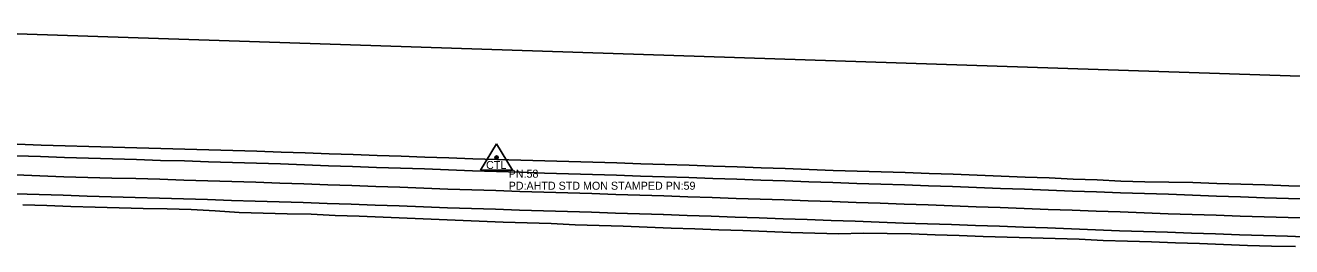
# Model space of a CAD drawing. Extents: x 976456 to 985170, y 1525951 to 1527080.
# Drawn here: x 979231 to 980022, y 1526411 to 1526549 of the extents above; entities that cross this region are included whole.
import ezdxf

# ---------------------------------------------------------------- set-up
doc = ezdxf.new("R2010")
doc.units = 0
for name, color, linetype in [('S_EDGE_PAVEMENT', 7, 'Continuous'), ('S_FIBER_OPTIC_CABLE', 7, 'Continuous'), ('S_PAVEMENT_CROWN', 7, 'Continuous'), ('S_PRIMARY_CTL', 7, 'Continuous'), ('S_PRIMARY_CTL_ANNOT', 7, 'Continuous'), ('S_SHOULDER', 7, 'Continuous')]:
    doc.layers.add(name, color=color, linetype=linetype)

msp = doc.modelspace()

# ---------------------------------------------------------------- linework, layer by layer
at = {"layer": 'S_EDGE_PAVEMENT'}
for points in [[(979225.79, 1526467.52), (979240.78, 1526466.95), (979240.78, 1526466.95), (979255.77, 1526466.38), (979255.77, 1526466.38), (979270.65, 1526465.96), (979270.65, 1526465.96), (979285.64, 1526465.53), (979300.64, 1526465.09), (979315.63, 1526464.64), (979315.63, 1526464.64), (979330.62, 1526464.27), (979330.62, 1526464.27), (979345.62, 1526463.82), (979360.61, 1526463.38), (979375.67, 1526462.89), (979375.67, 1526462.89), (979390.66, 1526462.39), (979390.66, 1526462.39), (979405.65, 1526461.88), (979405.65, 1526461.88), (979420.64, 1526461.28), (979420.64, 1526461.28), (979435.63, 1526460.75), (979450.62, 1526460.22), (979465.61, 1526459.76), (979480.57, 1526459.28), (979480.57, 1526459.28), (979495.56, 1526458.64), (979510.55, 1526458.16), (979510.55, 1526458.16), (979525.54, 1526457.72), (979525.54, 1526457.72), (979540.54, 1526457.23), (979555.53, 1526456.76), (979570.52, 1526456.29), (979585.51, 1526455.81), (979600.51, 1526455.34), (979600.51, 1526455.34), (979615.5, 1526454.87), (979630.49, 1526454.39), (979645.59, 1526453.94), (979660.58, 1526453.36), (979675.58, 1526452.91), (979690.57, 1526452.38), (979705.56, 1526451.88), (979720.55, 1526451.33), (979720.55, 1526451.33), (979735.54, 1526450.74), (979750.53, 1526450.25), (979765.52, 1526449.72), (979780.42, 1526449.34), (979795.41, 1526448.79), (979810.4, 1526448.3), (979825.39, 1526447.81), (979840.38, 1526447.2), (979855.37, 1526446.63), (979870.36, 1526446.15), (979885.35, 1526445.5), (979885.35, 1526445.5), (979900.34, 1526445.01), (979915.27, 1526444.35), (979930.27, 1526443.92), (979945.26, 1526443.49), (979960.25, 1526442.88), (979975.24, 1526442.28), (979990.23, 1526441.85), (980005.23, 1526441.36), (980020.22, 1526440.83), (980035.21, 1526440.4)], [(979224.89, 1526443.83), (979239.88, 1526443.35), (979254.87, 1526442.89), (979269.96, 1526442.43), (979284.95, 1526441.99), (979284.95, 1526441.99), (979299.94, 1526441.55), (979299.94, 1526441.55), (979314.94, 1526441.09), (979329.93, 1526440.64), (979329.93, 1526440.64), (979344.92, 1526440.19), (979344.92, 1526440.19), (979359.91, 1526439.67), (979359.91, 1526439.67), (979374.86, 1526439.21), (979374.86, 1526439.21), (979389.85, 1526438.72), (979404.84, 1526438.29), (979404.84, 1526438.29), (979419.84, 1526437.83), (979434.83, 1526437.33), (979434.83, 1526437.33), (979449.82, 1526436.76), (979449.82, 1526436.76), (979464.81, 1526436.22), (979464.81, 1526436.22), (979479.82, 1526435.66), (979494.82, 1526435.11), (979509.81, 1526434.65), (979524.8, 1526434.17), (979539.79, 1526433.68), (979554.79, 1526433.22), (979569.78, 1526432.74), (979584.77, 1526432.27), (979584.77, 1526432.27), (979599.76, 1526431.8), (979614.76, 1526431.32), (979629.75, 1526430.81), (979629.75, 1526430.8), (979644.65, 1526430.3), (979659.64, 1526429.78), (979674.63, 1526429.23), (979689.63, 1526428.78), (979704.62, 1526428.26), (979719.61, 1526427.76), (979734.6, 1526427.26), (979749.59, 1526426.71), (979764.58, 1526426.12), (979764.58, 1526426.12), (979779.64, 1526425.58), (979779.64, 1526425.58), (979794.63, 1526425.08), (979794.63, 1526425.08), (979809.63, 1526424.6), (979809.63, 1526424.6), (979824.62, 1526424.09), (979839.61, 1526423.54), (979854.6, 1526423), (979869.59, 1526422.49), (979884.58, 1526421.9), (979884.58, 1526421.9), (979899.57, 1526421.34), (979914.6, 1526420.8), (979929.59, 1526420.3), (979944.58, 1526419.79), (979944.58, 1526419.79), (979959.58, 1526419.27), (979959.58, 1526419.27), (979974.57, 1526418.79), (979989.56, 1526418.26), (979989.56, 1526418.26), (980004.55, 1526417.78), (980019.54, 1526417.34), (980034.54, 1526416.85)]]:
    msp.add_lwpolyline(points, dxfattribs=at)
at = {"layer": 'S_FIBER_OPTIC_CABLE'}
msp.add_line((982227.16, 1526444.43), (979068.74, 1526548.75), dxfattribs=at)
at = {"layer": 'S_PAVEMENT_CROWN'}
msp.add_lwpolyline([(979225.33, 1526455.53), (979240.32, 1526454.96), (979240.32, 1526454.96), (979255.31, 1526454.45), (979270.3, 1526454), (979285.29, 1526453.63), (979285.29, 1526453.63), (979300.29, 1526453.32), (979315.28, 1526452.88), (979315.28, 1526452.88), (979330.27, 1526452.33), (979345.27, 1526451.89), (979345.27, 1526451.89), (979360.26, 1526451.43), (979375.26, 1526450.96), (979375.26, 1526450.96), (979390.25, 1526450.45), (979390.25, 1526450.45), (979405.24, 1526449.91), (979420.23, 1526449.48), (979420.23, 1526449.48), (979435.22, 1526448.89), (979435.22, 1526448.89), (979450.21, 1526448.4), (979465.21, 1526447.85), (979465.21, 1526447.85), (979480.19, 1526447.37), (979480.19, 1526447.37), (979495.18, 1526446.79), (979495.18, 1526446.79), (979510.18, 1526446.28), (979510.18, 1526446.28), (979525.17, 1526445.77), (979525.17, 1526445.77), (979540.16, 1526445.29), (979555.15, 1526444.83), (979555.15, 1526444.83), (979570.14, 1526444.32), (979585.14, 1526443.92), (979600.13, 1526443.43), (979600.13, 1526443.43), (979615.12, 1526442.95), (979615.12, 1526442.95), (979630.11, 1526442.48), (979645.11, 1526441.95), (979645.11, 1526441.95), (979660.11, 1526441.42), (979660.11, 1526441.42), (979675.1, 1526440.88), (979675.1, 1526440.88), (979690.09, 1526440.39), (979690.09, 1526440.39), (979705.09, 1526440.08), (979705.09, 1526440.08), (979720.08, 1526439.51), (979720.08, 1526439.51), (979735.07, 1526438.93), (979735.07, 1526438.93), (979750.06, 1526438.48), (979765.05, 1526437.97), (979765.05, 1526437.97), (979780.03, 1526437.44), (979795.02, 1526436.95), (979795.02, 1526436.95), (979810.01, 1526436.37), (979810.01, 1526436.37), (979825, 1526435.78), (979839.99, 1526435.29), (979854.98, 1526434.72), (979854.98, 1526434.72), (979869.97, 1526434.09), (979884.96, 1526433.53), (979884.96, 1526433.53), (979899.95, 1526433.01), (979914.93, 1526432.47), (979914.93, 1526432.47), (979929.93, 1526432), (979929.93, 1526432), (979944.92, 1526431.4), (979944.92, 1526431.4), (979959.91, 1526430.89), (979974.9, 1526430.44), (979974.9, 1526430.44), (979989.89, 1526429.93), (980004.89, 1526429.5), (980004.89, 1526429.5), (980019.88, 1526429.03), (980034.87, 1526428.52)], dxfattribs=at)
at = {"layer": 'S_PRIMARY_CTL'}
for p, q in [((979525.6, 1526475.03), (979515.56, 1526458.52)), ((979525.6, 1526475.03), (979535.42, 1526458.52)), ((979515.56, 1526458.52), (979535.42, 1526458.52))]:
    msp.add_line(p, q, dxfattribs=at)
for radius in [1.04, 0.609, 0.344]:
    msp.add_circle((979525.6, 1526466.33), radius, dxfattribs=at)
at = {"layer": 'S_SHOULDER'}
for points in [[(979226.07, 1526474.76), (979241.06, 1526474.19), (979256.05, 1526473.62), (979270.87, 1526473.34), (979285.86, 1526472.9), (979300.86, 1526472.46), (979315.85, 1526471.97), (979330.84, 1526471.59), (979345.84, 1526471.15), (979360.83, 1526470.81), (979375.92, 1526470.31), (979390.92, 1526469.82), (979405.91, 1526469.3), (979420.9, 1526468.78), (979435.89, 1526468.2), (979450.88, 1526467.67), (979465.87, 1526467.21), (979480.81, 1526466.73), (979495.8, 1526466.2), (979510.79, 1526465.68), (979525.79, 1526465.24), (979540.78, 1526464.75), (979555.77, 1526464.43), (979570.77, 1526463.95), (979585.76, 1526463.48), (979600.75, 1526463.01), (979615.74, 1526462.5), (979630.74, 1526462.03), (979645.9, 1526461.57), (979660.89, 1526461), (979675.88, 1526460.54), (979690.87, 1526460.01), (979705.87, 1526459.51), (979720.86, 1526458.97), (979735.84, 1526458.37), (979750.84, 1526457.92), (979765.83, 1526457.4), (979780.67, 1526456.98), (979795.66, 1526456.42), (979810.65, 1526455.97), (979825.65, 1526455.48), (979840.63, 1526454.79), (979855.62, 1526454.16), (979870.61, 1526453.67), (979885.59, 1526452.96), (979900.59, 1526452.47), (979915.49, 1526451.75), (979930.48, 1526451.32), (979945.48, 1526451.07), (979960.48, 1526450.84), (979975.47, 1526450.25), (979990.47, 1526449.83), (980005.46, 1526449.36), (980020.45, 1526448.84), (980035.44, 1526448.3)], [(979229.76, 1526436.84), (979244.75, 1526436.44), (979259.75, 1526435.96), (979274.89, 1526435.5), (979289.88, 1526435.05), (979304.88, 1526434.69), (979319.87, 1526434.34), (979334.87, 1526433.95), (979349.85, 1526433.26), (979364.83, 1526432.21), (979379.73, 1526431.63), (979394.73, 1526431.38), (979409.73, 1526431.12), (979424.72, 1526430.33), (979439.71, 1526429.79), (979454.7, 1526429.19), (979469.73, 1526428.67), (979484.72, 1526428), (979499.7, 1526427.28), (979514.7, 1526426.76), (979529.68, 1526426.16), (979544.68, 1526425.71), (979559.67, 1526425.27), (979574.66, 1526424.54), (979589.65, 1526424.08), (979604.64, 1526423.61), (979619.63, 1526423.05), (979634.62, 1526422.38), (979649.45, 1526421.89), (979664.44, 1526421.35), (979679.44, 1526420.85), (979694.43, 1526420.38), (979709.42, 1526419.78), (979724.41, 1526419.26), (979739.41, 1526418.94), (979754.43, 1526419.19), (979769.44, 1526419.03), (979784.56, 1526418.8), (979799.55, 1526418.22), (979814.54, 1526417.72), (979829.53, 1526417.27), (979844.52, 1526416.8), (979859.52, 1526416.35), (979874.51, 1526415.86), (979889.5, 1526415.44), (979904.49, 1526414.8), (979919.55, 1526414.29), (979934.54, 1526413.85), (979949.53, 1526413.33), (979964.53, 1526412.81), (979979.51, 1526412.19), (979994.5, 1526411.5), (980009.49, 1526411.07), (980024.49, 1526410.89)]]:
    msp.add_lwpolyline(points, dxfattribs=at)

# ---------------------------------------------------------------- texts
at = {"layer": 'S_PRIMARY_CTL'}
msp.add_text('CTL', height=5, rotation=360, dxfattribs=at).set_placement((979519.01, 1526459.26))
at = {"layer": 'S_PRIMARY_CTL_ANNOT'}
for s, p in [('PN:58', (979533.1, 1526453.83)), ('PD:AHTD STD MON STAMPED PN:59', (979533.1, 1526446.33))]:
    msp.add_text(s, height=5, dxfattribs=at).set_placement(p)

doc.saveas('drawing.dxf')
